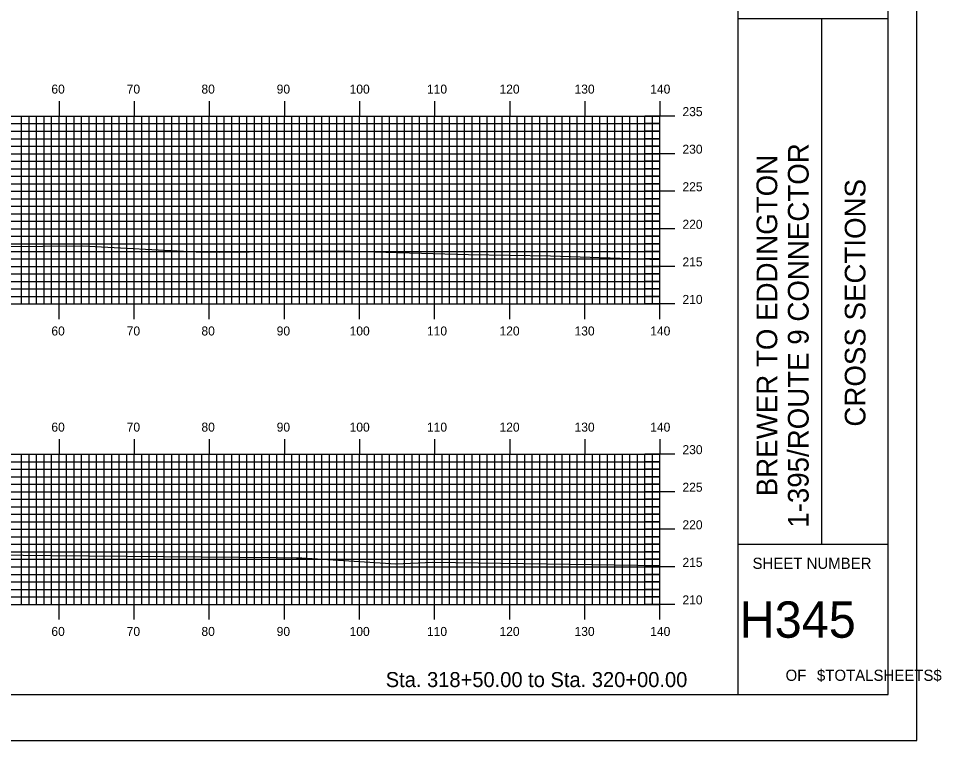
# Model space of a CAD drawing. Extents: x 1820031 to 1820374, y 442591 to 442811.
# Drawn here: x 1820251.3 to 1820374.2, y 442590.5 to 442686.7 of the extents above; entities that cross this region are included whole.
import ezdxf

# ---------------------------------------------------------------- set-up
doc = ezdxf.new("R2010")
doc.units = 0
for name, color, linetype in [('BORDER', 7, 'Continuous'), ('H_V ANNOTATION', 7, 'Continuous'), ('MAJOR', 7, 'Continuous'), ('MINOR', 7, 'Continuous'), ('PLOT BOUNDARY', 7, 'Continuous'), ('S_Roadway_Centerline', 7, 'Continuous')]:
    doc.layers.add(name, color=color, linetype=linetype)

msp = doc.modelspace()

# ---------------------------------------------------------------- linework, layer by layer
at = {"layer": 'BORDER'}
for p, q in [((1820347.09, 442596.67), (1820347.09, 442806.67)), ((1820347.09, 442686.67), (1820367.09, 442686.67)), ((1820358.27, 442616.67), (1820358.27, 442686.67)), ((1820347.09, 442616.67), (1820367.09, 442616.67))]:
    msp.add_line(p, q, dxfattribs=at)
msp.add_lwpolyline([(1820047.09, 442596.67), (1820367.09, 442596.67), (1820367.09, 442806.67), (1820047.09, 442806.67)], close=True, dxfattribs=at)
at = {"layer": 'MAJOR'}
for p, q in [((1820256.69, 442675.67), (1820256.69, 442673.67)), ((1820266.69, 442675.67), (1820266.69, 442673.67)), ((1820276.69, 442675.67), (1820276.69, 442673.67)), ((1820286.69, 442675.67), (1820286.69, 442673.67)), ((1820296.69, 442675.67), (1820296.69, 442673.67)), ((1820306.69, 442675.67), (1820306.69, 442673.67)), ((1820316.69, 442675.67), (1820316.69, 442673.67)), ((1820326.69, 442675.67), (1820326.69, 442673.67)), ((1820336.69, 442675.67), (1820336.69, 442673.67)), ((1820056.69, 442673.67), (1820336.69, 442673.67)), ((1820056.69, 442673.67), (1820336.69, 442673.67)), ((1820256.69, 442648.67), (1820256.69, 442673.67)), ((1820266.69, 442648.67), (1820266.69, 442673.67)), ((1820276.69, 442648.67), (1820276.69, 442673.67)), ((1820286.69, 442648.67), (1820286.69, 442673.67)), ((1820296.69, 442648.67), (1820296.69, 442673.67)), ((1820306.69, 442648.67), (1820306.69, 442673.67)), ((1820316.69, 442648.67), (1820316.69, 442673.67)), ((1820326.69, 442648.67), (1820326.69, 442673.67)), ((1820338.69, 442673.67), (1820334.69, 442673.67)), ((1820336.69, 442648.67), (1820336.69, 442673.67)), ((1820336.69, 442648.67), (1820336.69, 442673.67)), ((1820056.69, 442668.67), (1820336.69, 442668.67)), ((1820338.69, 442668.67), (1820334.69, 442668.67)), ((1820056.69, 442663.67), (1820336.69, 442663.67)), ((1820338.69, 442663.67), (1820334.69, 442663.67)), ((1820056.69, 442658.67), (1820336.69, 442658.67)), ((1820338.69, 442658.67), (1820334.69, 442658.67)), ((1820056.69, 442653.67), (1820336.69, 442653.67)), ((1820338.69, 442653.67), (1820334.69, 442653.67)), ((1820056.69, 442648.67), (1820336.69, 442648.67)), ((1820056.69, 442648.67), (1820336.69, 442648.67)), ((1820256.69, 442646.66), (1820256.69, 442648.67)), ((1820266.69, 442646.66), (1820266.69, 442648.67)), ((1820276.69, 442646.66), (1820276.69, 442648.67)), ((1820286.69, 442646.66), (1820286.69, 442648.67)), ((1820296.69, 442646.66), (1820296.69, 442648.67)), ((1820306.69, 442646.66), (1820306.69, 442648.67)), ((1820316.69, 442646.66), (1820316.69, 442648.67)), ((1820326.69, 442646.66), (1820326.69, 442648.67)), ((1820338.69, 442648.67), (1820334.69, 442648.67)), ((1820336.69, 442646.66), (1820336.69, 442648.67)), ((1820256.69, 442630.67), (1820256.69, 442628.67)), ((1820266.69, 442630.67), (1820266.69, 442628.67)), ((1820276.69, 442630.67), (1820276.69, 442628.67)), ((1820286.69, 442630.67), (1820286.69, 442628.67)), ((1820296.69, 442630.67), (1820296.69, 442628.67)), ((1820306.69, 442630.67), (1820306.69, 442628.67)), ((1820316.69, 442630.67), (1820316.69, 442628.67)), ((1820326.69, 442630.67), (1820326.69, 442628.67)), ((1820336.69, 442630.67), (1820336.69, 442628.67)), ((1820056.69, 442628.67), (1820336.69, 442628.67)), ((1820056.69, 442628.67), (1820336.69, 442628.67)), ((1820256.69, 442608.67), (1820256.69, 442628.67)), ((1820266.69, 442608.67), (1820266.69, 442628.67)), ((1820276.69, 442608.67), (1820276.69, 442628.67)), ((1820286.69, 442608.67), (1820286.69, 442628.67)), ((1820296.69, 442608.67), (1820296.69, 442628.67)), ((1820306.69, 442608.67), (1820306.69, 442628.67)), ((1820316.69, 442608.67), (1820316.69, 442628.67)), ((1820326.69, 442608.67), (1820326.69, 442628.67)), ((1820338.69, 442628.67), (1820334.69, 442628.67)), ((1820336.69, 442608.67), (1820336.69, 442628.67)), ((1820336.69, 442608.67), (1820336.69, 442628.67)), ((1820056.69, 442623.67), (1820336.69, 442623.67)), ((1820338.69, 442623.67), (1820334.69, 442623.67)), ((1820056.69, 442618.67), (1820336.69, 442618.67)), ((1820338.69, 442618.67), (1820334.69, 442618.67)), ((1820056.69, 442613.67), (1820336.69, 442613.67)), ((1820338.69, 442613.67), (1820334.69, 442613.67)), ((1820056.69, 442608.67), (1820336.69, 442608.67)), ((1820056.69, 442608.67), (1820336.69, 442608.67)), ((1820256.69, 442606.66), (1820256.69, 442608.67)), ((1820266.69, 442606.66), (1820266.69, 442608.67)), ((1820276.69, 442606.66), (1820276.69, 442608.67)), ((1820286.69, 442606.66), (1820286.69, 442608.67)), ((1820296.69, 442606.66), (1820296.69, 442608.67)), ((1820306.69, 442606.66), (1820306.69, 442608.67)), ((1820316.69, 442606.66), (1820316.69, 442608.67)), ((1820326.69, 442606.66), (1820326.69, 442608.67)), ((1820338.69, 442608.67), (1820334.69, 442608.67)), ((1820336.69, 442606.66), (1820336.69, 442608.67))]:
    msp.add_line(p, q, dxfattribs=at)
at = {"layer": 'MINOR'}
for p, q in [((1820251.69, 442648.67), (1820251.69, 442673.67)), ((1820252.69, 442648.67), (1820252.69, 442673.67)), ((1820253.69, 442648.67), (1820253.69, 442673.67)), ((1820254.69, 442648.67), (1820254.69, 442673.67)), ((1820255.69, 442648.67), (1820255.69, 442673.67)), ((1820257.69, 442648.67), (1820257.69, 442673.67)), ((1820258.69, 442648.67), (1820258.69, 442673.67)), ((1820259.69, 442648.67), (1820259.69, 442673.67)), ((1820260.69, 442648.67), (1820260.69, 442673.67)), ((1820261.69, 442648.67), (1820261.69, 442673.67)), ((1820262.69, 442648.67), (1820262.69, 442673.67)), ((1820263.69, 442648.67), (1820263.69, 442673.67)), ((1820264.69, 442648.67), (1820264.69, 442673.67)), ((1820265.69, 442648.67), (1820265.69, 442673.67)), ((1820267.69, 442648.67), (1820267.69, 442673.67)), ((1820268.69, 442648.67), (1820268.69, 442673.67)), ((1820269.69, 442648.67), (1820269.69, 442673.67)), ((1820270.69, 442648.67), (1820270.69, 442673.67)), ((1820271.69, 442648.67), (1820271.69, 442673.67)), ((1820272.69, 442648.67), (1820272.69, 442673.67)), ((1820273.69, 442648.67), (1820273.69, 442673.67)), ((1820274.69, 442648.67), (1820274.69, 442673.67)), ((1820275.69, 442648.67), (1820275.69, 442673.67)), ((1820277.69, 442648.67), (1820277.69, 442673.67)), ((1820278.69, 442648.67), (1820278.69, 442673.67)), ((1820279.69, 442648.67), (1820279.69, 442673.67)), ((1820280.69, 442648.67), (1820280.69, 442673.67)), ((1820281.69, 442648.67), (1820281.69, 442673.67)), ((1820282.69, 442648.67), (1820282.69, 442673.67)), ((1820283.69, 442648.67), (1820283.69, 442673.67)), ((1820284.69, 442648.67), (1820284.69, 442673.67)), ((1820285.69, 442648.67), (1820285.69, 442673.67)), ((1820287.69, 442648.67), (1820287.69, 442673.67)), ((1820288.69, 442648.67), (1820288.69, 442673.67)), ((1820289.69, 442648.67), (1820289.69, 442673.67)), ((1820290.69, 442648.67), (1820290.69, 442673.67)), ((1820291.69, 442648.67), (1820291.69, 442673.67)), ((1820292.69, 442648.67), (1820292.69, 442673.67)), ((1820293.69, 442648.67), (1820293.69, 442673.67)), ((1820294.69, 442648.67), (1820294.69, 442673.67)), ((1820295.69, 442648.67), (1820295.69, 442673.67)), ((1820297.69, 442648.67), (1820297.69, 442673.67)), ((1820298.69, 442648.67), (1820298.69, 442673.67)), ((1820299.69, 442648.67), (1820299.69, 442673.67)), ((1820300.69, 442648.67), (1820300.69, 442673.67)), ((1820301.69, 442648.67), (1820301.69, 442673.67)), ((1820302.69, 442648.67), (1820302.69, 442673.67)), ((1820303.69, 442648.67), (1820303.69, 442673.67)), ((1820304.69, 442648.67), (1820304.69, 442673.67)), ((1820305.69, 442648.67), (1820305.69, 442673.67)), ((1820307.69, 442648.67), (1820307.69, 442673.67)), ((1820308.69, 442648.67), (1820308.69, 442673.67)), ((1820309.69, 442648.67), (1820309.69, 442673.67)), ((1820310.69, 442648.67), (1820310.69, 442673.67)), ((1820311.69, 442648.67), (1820311.69, 442673.67)), ((1820312.69, 442648.67), (1820312.69, 442673.67)), ((1820313.69, 442648.67), (1820313.69, 442673.67)), ((1820314.69, 442648.67), (1820314.69, 442673.67)), ((1820315.69, 442648.67), (1820315.69, 442673.67)), ((1820317.69, 442648.67), (1820317.69, 442673.67)), ((1820318.69, 442648.67), (1820318.69, 442673.67)), ((1820319.69, 442648.67), (1820319.69, 442673.67)), ((1820320.69, 442648.67), (1820320.69, 442673.67)), ((1820321.69, 442648.67), (1820321.69, 442673.67)), ((1820322.69, 442648.67), (1820322.69, 442673.67)), ((1820323.69, 442648.67), (1820323.69, 442673.67)), ((1820324.69, 442648.67), (1820324.69, 442673.67)), ((1820325.69, 442648.67), (1820325.69, 442673.67)), ((1820327.69, 442648.67), (1820327.69, 442673.67)), ((1820328.69, 442648.67), (1820328.69, 442673.67)), ((1820329.69, 442648.67), (1820329.69, 442673.67)), ((1820330.69, 442648.67), (1820330.69, 442673.67)), ((1820331.69, 442648.67), (1820331.69, 442673.67)), ((1820332.69, 442648.67), (1820332.69, 442673.67)), ((1820333.69, 442648.67), (1820333.69, 442673.67)), ((1820334.69, 442648.67), (1820334.69, 442673.67)), ((1820335.69, 442648.67), (1820335.69, 442673.67)), ((1820056.69, 442672.67), (1820336.69, 442672.67)), ((1820056.69, 442671.67), (1820336.69, 442671.67)), ((1820336.69, 442672.67), (1820334.69, 442672.67)), ((1820336.69, 442671.67), (1820334.69, 442671.67)), ((1820056.69, 442670.67), (1820336.69, 442670.67)), ((1820336.69, 442670.67), (1820334.69, 442670.67)), ((1820056.69, 442669.67), (1820336.69, 442669.67)), ((1820336.69, 442669.67), (1820334.69, 442669.67)), ((1820056.69, 442667.67), (1820336.69, 442667.67)), ((1820056.69, 442666.67), (1820336.69, 442666.67)), ((1820336.69, 442667.67), (1820334.69, 442667.67)), ((1820336.69, 442666.67), (1820334.69, 442666.67)), ((1820056.69, 442665.67), (1820336.69, 442665.67)), ((1820336.69, 442665.67), (1820334.69, 442665.67)), ((1820056.69, 442664.67), (1820336.69, 442664.67)), ((1820336.69, 442664.67), (1820334.69, 442664.67)), ((1820056.69, 442662.67), (1820336.69, 442662.67)), ((1820336.69, 442662.67), (1820334.69, 442662.67)), ((1820056.69, 442661.67), (1820336.69, 442661.67)), ((1820056.69, 442660.67), (1820336.69, 442660.67)), ((1820336.69, 442661.67), (1820334.69, 442661.67)), ((1820336.69, 442660.67), (1820334.69, 442660.67)), ((1820056.69, 442659.67), (1820336.69, 442659.67)), ((1820336.69, 442659.67), (1820334.69, 442659.67)), ((1820056.69, 442657.67), (1820336.69, 442657.67)), ((1820336.69, 442657.67), (1820334.69, 442657.67)), ((1820056.69, 442656.67), (1820336.69, 442656.67)), ((1820056.69, 442655.67), (1820336.69, 442655.67)), ((1820336.69, 442656.67), (1820334.69, 442656.67)), ((1820336.69, 442655.67), (1820334.69, 442655.67)), ((1820056.69, 442654.67), (1820336.69, 442654.67)), ((1820336.69, 442654.67), (1820334.69, 442654.67)), ((1820056.69, 442652.67), (1820336.69, 442652.67)), ((1820336.69, 442652.67), (1820334.69, 442652.67)), ((1820056.69, 442651.67), (1820336.69, 442651.67)), ((1820056.69, 442650.67), (1820336.69, 442650.67)), ((1820336.69, 442651.67), (1820334.69, 442651.67)), ((1820336.69, 442650.67), (1820334.69, 442650.67)), ((1820056.69, 442649.67), (1820336.69, 442649.67)), ((1820336.69, 442649.67), (1820334.69, 442649.67)), ((1820251.69, 442608.67), (1820251.69, 442628.67)), ((1820252.69, 442608.67), (1820252.69, 442628.67)), ((1820253.69, 442608.67), (1820253.69, 442628.67)), ((1820254.69, 442608.67), (1820254.69, 442628.67)), ((1820255.69, 442608.67), (1820255.69, 442628.67)), ((1820257.69, 442608.67), (1820257.69, 442628.67)), ((1820258.69, 442608.67), (1820258.69, 442628.67)), ((1820259.69, 442608.67), (1820259.69, 442628.67)), ((1820260.69, 442608.67), (1820260.69, 442628.67)), ((1820261.69, 442608.67), (1820261.69, 442628.67)), ((1820262.69, 442608.67), (1820262.69, 442628.67)), ((1820263.69, 442608.67), (1820263.69, 442628.67)), ((1820264.69, 442608.67), (1820264.69, 442628.67)), ((1820265.69, 442608.67), (1820265.69, 442628.67)), ((1820267.69, 442608.67), (1820267.69, 442628.67)), ((1820268.69, 442608.67), (1820268.69, 442628.67)), ((1820269.69, 442608.67), (1820269.69, 442628.67)), ((1820270.69, 442608.67), (1820270.69, 442628.67)), ((1820271.69, 442608.67), (1820271.69, 442628.67)), ((1820272.69, 442608.67), (1820272.69, 442628.67)), ((1820273.69, 442608.67), (1820273.69, 442628.67)), ((1820274.69, 442608.67), (1820274.69, 442628.67)), ((1820275.69, 442608.67), (1820275.69, 442628.67)), ((1820277.69, 442608.67), (1820277.69, 442628.67)), ((1820278.69, 442608.67), (1820278.69, 442628.67)), ((1820279.69, 442608.67), (1820279.69, 442628.67)), ((1820280.69, 442608.67), (1820280.69, 442628.67)), ((1820281.69, 442608.67), (1820281.69, 442628.67)), ((1820282.69, 442608.67), (1820282.69, 442628.67)), ((1820283.69, 442608.67), (1820283.69, 442628.67)), ((1820284.69, 442608.67), (1820284.69, 442628.67)), ((1820285.69, 442608.67), (1820285.69, 442628.67)), ((1820287.69, 442608.67), (1820287.69, 442628.67)), ((1820288.69, 442608.67), (1820288.69, 442628.67)), ((1820289.69, 442608.67), (1820289.69, 442628.67)), ((1820290.69, 442608.67), (1820290.69, 442628.67)), ((1820291.69, 442608.67), (1820291.69, 442628.67)), ((1820292.69, 442608.67), (1820292.69, 442628.67)), ((1820293.69, 442608.67), (1820293.69, 442628.67)), ((1820294.69, 442608.67), (1820294.69, 442628.67)), ((1820295.69, 442608.67), (1820295.69, 442628.67)), ((1820297.69, 442608.67), (1820297.69, 442628.67)), ((1820298.69, 442608.67), (1820298.69, 442628.67)), ((1820299.69, 442608.67), (1820299.69, 442628.67)), ((1820300.69, 442608.67), (1820300.69, 442628.67)), ((1820301.69, 442608.67), (1820301.69, 442628.67)), ((1820302.69, 442608.67), (1820302.69, 442628.67)), ((1820303.69, 442608.67), (1820303.69, 442628.67)), ((1820304.69, 442608.67), (1820304.69, 442628.67)), ((1820305.69, 442608.67), (1820305.69, 442628.67)), ((1820307.69, 442608.67), (1820307.69, 442628.67)), ((1820308.69, 442608.67), (1820308.69, 442628.67)), ((1820309.69, 442608.67), (1820309.69, 442628.67)), ((1820310.69, 442608.67), (1820310.69, 442628.67)), ((1820311.69, 442608.67), (1820311.69, 442628.67)), ((1820312.69, 442608.67), (1820312.69, 442628.67)), ((1820313.69, 442608.67), (1820313.69, 442628.67)), ((1820314.69, 442608.67), (1820314.69, 442628.67)), ((1820315.69, 442608.67), (1820315.69, 442628.67)), ((1820317.69, 442608.67), (1820317.69, 442628.67)), ((1820318.69, 442608.67), (1820318.69, 442628.67)), ((1820319.69, 442608.67), (1820319.69, 442628.67)), ((1820320.69, 442608.67), (1820320.69, 442628.67)), ((1820321.69, 442608.67), (1820321.69, 442628.67)), ((1820322.69, 442608.67), (1820322.69, 442628.67)), ((1820323.69, 442608.67), (1820323.69, 442628.67)), ((1820324.69, 442608.67), (1820324.69, 442628.67)), ((1820325.69, 442608.67), (1820325.69, 442628.67)), ((1820327.69, 442608.67), (1820327.69, 442628.67)), ((1820328.69, 442608.67), (1820328.69, 442628.67)), ((1820329.69, 442608.67), (1820329.69, 442628.67)), ((1820330.69, 442608.67), (1820330.69, 442628.67)), ((1820331.69, 442608.67), (1820331.69, 442628.67)), ((1820332.69, 442608.67), (1820332.69, 442628.67)), ((1820333.69, 442608.67), (1820333.69, 442628.67)), ((1820334.69, 442608.67), (1820334.69, 442628.67)), ((1820335.69, 442608.67), (1820335.69, 442628.67)), ((1820056.69, 442627.67), (1820336.69, 442627.67)), ((1820336.69, 442627.67), (1820334.69, 442627.67)), ((1820056.69, 442626.67), (1820336.69, 442626.67)), ((1820336.69, 442626.67), (1820334.69, 442626.67)), ((1820056.69, 442625.67), (1820336.69, 442625.67)), ((1820336.69, 442625.67), (1820334.69, 442625.67)), ((1820056.69, 442624.67), (1820336.69, 442624.67)), ((1820336.69, 442624.67), (1820334.69, 442624.67)), ((1820056.69, 442622.67), (1820336.69, 442622.67)), ((1820336.69, 442622.67), (1820334.69, 442622.67)), ((1820056.69, 442621.67), (1820336.69, 442621.67)), ((1820336.69, 442621.67), (1820334.69, 442621.67)), ((1820056.69, 442620.67), (1820336.69, 442620.67)), ((1820336.69, 442620.67), (1820334.69, 442620.67)), ((1820056.69, 442619.67), (1820336.69, 442619.67)), ((1820336.69, 442619.67), (1820334.69, 442619.67)), ((1820056.69, 442617.67), (1820336.69, 442617.67)), ((1820336.69, 442617.67), (1820334.69, 442617.67)), ((1820056.69, 442616.67), (1820336.69, 442616.67)), ((1820336.69, 442616.67), (1820334.69, 442616.67)), ((1820056.69, 442615.67), (1820336.69, 442615.67)), ((1820336.69, 442615.67), (1820334.69, 442615.67)), ((1820056.69, 442614.67), (1820336.69, 442614.67)), ((1820336.69, 442614.67), (1820334.69, 442614.67)), ((1820056.69, 442612.67), (1820336.69, 442612.67)), ((1820336.69, 442612.67), (1820334.69, 442612.67)), ((1820056.69, 442611.67), (1820336.69, 442611.67)), ((1820336.69, 442611.67), (1820334.69, 442611.67)), ((1820056.69, 442610.67), (1820336.69, 442610.67)), ((1820336.69, 442610.67), (1820334.69, 442610.67)), ((1820056.69, 442609.67), (1820336.69, 442609.67)), ((1820336.69, 442609.67), (1820334.69, 442609.67))]:
    msp.add_line(p, q, dxfattribs=at)
at = {"layer": 'PLOT BOUNDARY'}
msp.add_lwpolyline([(1820030.9, 442590.55), (1820370.9, 442590.55), (1820370.9, 442810.55), (1820030.9, 442810.55)], close=True, dxfattribs=at)
at = {"layer": 'S_Roadway_Centerline'}
for points in [[(1820249.22, 442656.31), (1820259.82, 442656.42), (1820274.92, 442655.61), (1820278.02, 442655.58), (1820293.94, 442655.74), (1820311.19, 442655.24), (1820322.13, 442655.07), (1820336.69, 442654.58)], [(1820248.06, 442615.29), (1820255.72, 442615.2), (1820285.76, 442614.92), (1820288.29, 442614.86), (1820289.02, 442614.85), (1820301.54, 442614.08), (1820306.44, 442614.28), (1820336.69, 442613.86)]]:
    msp.add_lwpolyline(points, dxfattribs=at)

# ---------------------------------------------------------------- texts
at = {"layer": 'BORDER'}
for s, p in [('1-395/ROUTE 9 CONNECTOR', (1820356.49, 442618.87)), ('BREWER TO EDDINGTON', (1820352.31, 442623.07)), ('CROSS SECTIONS', (1820364.06, 442632.34))]:
    msp.add_text(s, height=2.7557, rotation=90, dxfattribs=at).set_placement(p)
for s, height, p in [('SHEET NUMBER', 1.4905, (1820349.02, 442613.4)), ('H345', 4.839, (1820347.3, 442604.23)), ('OF', 1.491, (1820353.42, 442598.49)), ('$TOTALSHEETS$', 1.4905, (1820357.6, 442598.49))]:
    msp.add_text(s, height=height, dxfattribs=at).set_placement(p)
at = {"layer": 'H_V ANNOTATION'}
for s, height, p in [('60', 1.2, (1820255.66, 442676.67)), ('70', 1.2, (1820265.69, 442676.67)), ('80', 1.2, (1820275.64, 442676.67)), ('90', 1.2, (1820285.66, 442676.67)), ('100', 1.2, (1820295.37, 442676.67)), ('110', 1.2, (1820305.67, 442676.67)), ('120', 1.2, (1820315.33, 442676.67)), ('130', 1.2, (1820325.32, 442676.67)), ('140', 1.2, (1820335.4, 442676.67)), ('235', 1.2, (1820339.69, 442673.67)), ('230', 1.2, (1820339.69, 442668.67)), ('225', 1.2, (1820339.69, 442663.67)), ('220', 1.2, (1820339.69, 442658.67)), ('215', 1.2, (1820339.69, 442653.67)), ('210', 1.2, (1820339.69, 442648.67)), ('60', 1.2, (1820255.66, 442644.47)), ('70', 1.2, (1820265.69, 442644.47)), ('80', 1.2, (1820275.64, 442644.47)), ('90', 1.2, (1820285.66, 442644.47)), ('100', 1.2, (1820295.37, 442644.47)), ('110', 1.2, (1820305.67, 442644.47)), ('120', 1.2, (1820315.33, 442644.47)), ('130', 1.2, (1820325.32, 442644.47)), ('140', 1.2, (1820335.4, 442644.47)), ('60', 1.2, (1820255.66, 442631.67)), ('70', 1.2, (1820265.69, 442631.67)), ('80', 1.2, (1820275.64, 442631.67)), ('90', 1.2, (1820285.66, 442631.67)), ('100', 1.2, (1820295.37, 442631.67)), ('110', 1.2, (1820305.67, 442631.67)), ('120', 1.2, (1820315.33, 442631.67)), ('130', 1.2, (1820325.32, 442631.67)), ('140', 1.2, (1820335.4, 442631.67)), ('230', 1.2, (1820339.69, 442628.67)), ('225', 1.2, (1820339.69, 442623.67)), ('220', 1.2, (1820339.69, 442618.67)), ('215', 1.2, (1820339.69, 442613.67)), ('210', 1.2, (1820339.69, 442608.67)), ('60', 1.2, (1820255.66, 442604.47)), ('70', 1.2, (1820265.69, 442604.47)), ('80', 1.2, (1820275.64, 442604.47)), ('90', 1.2, (1820285.66, 442604.47)), ('100', 1.2, (1820295.37, 442604.47)), ('110', 1.2, (1820305.67, 442604.47)), ('120', 1.2, (1820315.33, 442604.47)), ('130', 1.2, (1820325.32, 442604.47)), ('140', 1.2, (1820335.4, 442604.47)), ('Sta. 318+50.00 to Sta. 320+00.00', 2.0004, (1820300.18, 442597.66))]:
    msp.add_text(s, height=height, dxfattribs=at).set_placement(p)

doc.saveas('drawing.dxf')
